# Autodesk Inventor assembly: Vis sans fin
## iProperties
Shininess: 64.0
Length Units: 11269
Angle Units: 11279
Time Units: 11290
Mass Units: 11283
Length Display Precision: 3
Angle Display Precision: 2
Compacted: True
Created: 2003-05
Part Number: Vis sans fin
Document SubType Name: Assembly
Designer: Philippe
Density: 0.0
Volumn: 0.0
Area: 0.0
PropertySet Name: Model Information
Control State: 0
Master: False
Checked Out: False
Author: Philippe
